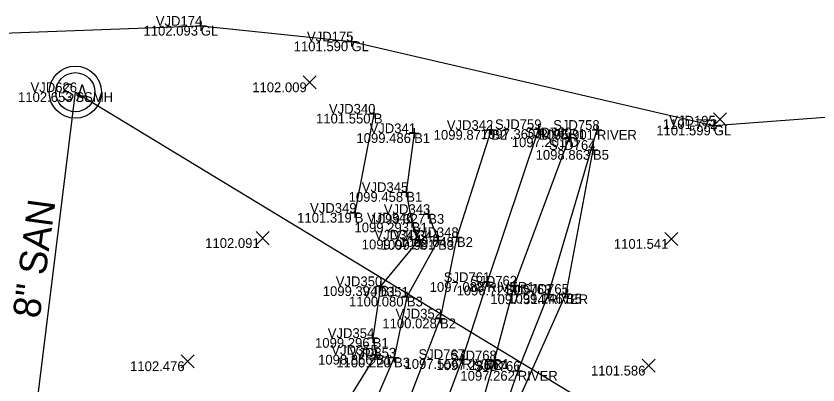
# Model space of a CAD drawing. Extents: x 1629915 to 1630675, y 484401 to 484601.
# Drawn here: x 1630255.7 to 1630337.7, y 484537.9 to 484575.6 of the extents above; entities that cross this region are included whole.
import ezdxf

# ---------------------------------------------------------------- set-up
doc = ezdxf.new("R2010")
doc.units = 0
for name, color, linetype in [('DR_X_Ditch', 7, 'Continuous'), ('GK_Drainage_Nodes', 7, 'Continuous'), ('HY_X_Water_Edge', 7, 'Continuous'), ('SV_X_Break_Lines', 7, 'Continuous'), ('SV_X_Random_Point', 7, 'Continuous'), ('SV_X_Shot_Marker', 7, 'Continuous'), ('SV_X_Text_Comment', 7, 'Continuous'), ('SV_X_Text_Elevation', 7, 'Continuous'), ('SV_X_Text_Name', 7, 'Continuous'), ('TX_X_20', 7, 'Continuous'), ('UT_X_Gas', 7, 'Continuous'), ('UT_X_Sanitary_Cells', 7, 'Continuous'), ('UT_X_Sanitary_Line', 7, 'Continuous')]:
    doc.layers.add(name, color=color, linetype=linetype)

msp = doc.modelspace()

# ---------------------------------------------------------------- linework, layer by layer
at = {"layer": 'DR_X_Ditch'}
msp.add_lwpolyline([(1630312.285, 484563.174), (1630306.638, 484548.008), (1630304.593, 484540.369), (1630301.212, 484528.393), (1630285.162, 484501.971), (1630282.791, 484487.89), (1630276.09, 484465.226), (1630270.913, 484444.523), (1630257.639, 484422.19), (1630254.188, 484411.475)], dxfattribs=at)
at = {"layer": 'GK_Drainage_Nodes'}
for p, q in [((1630261.76, 484569.794), (1630261.76, 484569.794)), ((1630261.76, 484567.794), (1630261.76, 484567.794)), ((1630261.76, 484567.794), (1630261.76, 484567.794)), ((1630261.76, 484567.794), (1630261.76, 484567.794)), ((1630261.76, 484565.794), (1630261.76, 484565.794))]:
    msp.add_line(p, q, dxfattribs=at)
msp.add_circle((1630261.76, 484567.794), 2, dxfattribs=at)
at = {"layer": 'HY_X_Water_Edge'}
for points in [[(1630309.149, 484564.014), (1630303.907, 484548.371), (1630301.335, 484540.498), (1630297.554, 484530.327), (1630293.047, 484517.737), (1630293.065, 484517.242), (1630286.863, 484512.402), (1630280.864, 484506.48), (1630276.95, 484506.557), (1630270.552, 484490.946), (1630261.424, 484466.626), (1630255.81, 484461.657), (1630255.926, 484458.148), (1630258.606, 484455.59), (1630264.105, 484457.697), (1630265.615, 484457.846), (1630266.742, 484455.334), (1630264.827, 484450.845), (1630263.176, 484437.258), (1630258.725, 484424.768), (1630254.124, 484415.998)], [(1630315.117, 484563.934), (1630310.133, 484547.118), (1630307.022, 484539.287), (1630303.337, 484528.643), (1630300.614, 484515.043), (1630303.987, 484512.284), (1630295.569, 484489.654), (1630286.814, 484467.342), (1630288.813, 484458.618), (1630286.633, 484457.39), (1630280.042, 484444.765), (1630267.68, 484419.987), (1630256.457, 484407.968)]]:
    msp.add_lwpolyline(points, dxfattribs=at)
at = {"layer": 'SV_X_Break_Lines'}
for points in [[(1630292.294, 484565.594), (1630290.337, 484555.453)], [(1630296.417, 484563.601), (1630295.615, 484557.584), (1630296.178, 484554.459), (1630296.937, 484552.722), (1630292.991, 484547.948), (1630292.183, 484542.654), (1630292.496, 484540.935), (1630289.335, 484535.783)], [(1630304.314, 484563.932), (1630300.799, 484552.969), (1630299.066, 484544.645), (1630294.605, 484533.045)], [(1630314.711, 484561.886), (1630311.942, 484547.182), (1630307.141, 484536.414), (1630304.819, 484528.662), (1630303.788, 484518.017)], [(1630297.86, 484555.334), (1630298.878, 484552.674), (1630295.673, 484546.879), (1630294.364, 484540.646), (1630291.461, 484533.951)]]:
    msp.add_lwpolyline(points, dxfattribs=at)
at = {"layer": 'SV_X_Random_Point'}
for p, q in [((1630285.071, 484568.127), (1630286.404, 484569.462)), ((1630285.071, 484569.462), (1630286.404, 484568.127)), ((1630327.059, 484564.358), (1630328.392, 484565.693)), ((1630327.059, 484565.693), (1630328.392, 484564.358)), ((1630280.257, 484552.196), (1630281.59, 484553.531)), ((1630280.257, 484553.531), (1630281.59, 484552.196)), ((1630322.065, 484552.107), (1630323.398, 484553.442)), ((1630322.065, 484553.442), (1630323.398, 484552.107)), ((1630272.594, 484539.599), (1630273.928, 484540.934)), ((1630272.594, 484540.934), (1630273.928, 484539.599)), ((1630319.74, 484539.15), (1630321.074, 484540.485)), ((1630319.74, 484540.485), (1630321.074, 484539.15))]:
    msp.add_line(p, q, dxfattribs=at)
at = {"layer": 'SV_X_Shot_Marker'}
for p, q in [((1630274.591, 484575.083), (1630274.591, 484574.083)), ((1630274.091, 484574.583), (1630275.091, 484574.583)), ((1630274.591, 484574.583), (1630274.591, 484574.583)), ((1630290.006, 484573.484), (1630290.006, 484572.484)), ((1630289.506, 484572.984), (1630290.506, 484572.984)), ((1630290.006, 484572.984), (1630290.006, 484572.984)), ((1630292.294, 484566.094), (1630292.294, 484565.094)), ((1630291.794, 484565.594), (1630292.794, 484565.594)), ((1630292.294, 484565.594), (1630292.294, 484565.594)), ((1630304.314, 484564.432), (1630304.314, 484563.432)), ((1630309.149, 484564.514), (1630309.149, 484563.514)), ((1630315.117, 484564.434), (1630315.117, 484563.434)), ((1630326.57, 484564.379), (1630327.57, 484564.379)), ((1630327.07, 484564.879), (1630327.07, 484563.879)), ((1630327.07, 484564.379), (1630327.07, 484564.379)), ((1630295.917, 484563.601), (1630296.917, 484563.601)), ((1630296.417, 484564.101), (1630296.417, 484563.101)), ((1630296.417, 484563.601), (1630296.417, 484563.601)), ((1630303.814, 484563.932), (1630304.814, 484563.932)), ((1630304.314, 484563.932), (1630304.314, 484563.932)), ((1630308.649, 484564.014), (1630309.649, 484564.014)), ((1630309.149, 484564.014), (1630309.149, 484564.014)), ((1630312.285, 484563.674), (1630312.285, 484562.674)), ((1630314.617, 484563.934), (1630315.617, 484563.934)), ((1630315.117, 484563.934), (1630315.117, 484563.934)), ((1630311.785, 484563.174), (1630312.785, 484563.174)), ((1630312.285, 484563.174), (1630312.285, 484563.174)), ((1630314.211, 484561.886), (1630315.211, 484561.886)), ((1630314.711, 484562.386), (1630314.711, 484561.386)), ((1630314.711, 484561.886), (1630314.711, 484561.886)), ((1630295.115, 484557.584), (1630296.115, 484557.584)), ((1630295.615, 484558.084), (1630295.615, 484557.084)), ((1630295.615, 484557.584), (1630295.615, 484557.584)), ((1630290.337, 484555.953), (1630290.337, 484554.953)), ((1630289.837, 484555.453), (1630290.837, 484555.453)), ((1630290.337, 484555.453), (1630290.337, 484555.453)), ((1630297.36, 484555.334), (1630298.36, 484555.334)), ((1630297.86, 484555.834), (1630297.86, 484554.834)), ((1630297.86, 484555.334), (1630297.86, 484555.334)), ((1630295.678, 484554.459), (1630296.678, 484554.459)), ((1630296.178, 484554.959), (1630296.178, 484553.959)), ((1630296.178, 484554.459), (1630296.178, 484554.459)), ((1630300.799, 484553.469), (1630300.799, 484552.469)), ((1630296.437, 484552.722), (1630297.437, 484552.722)), ((1630296.937, 484553.222), (1630296.937, 484552.222)), ((1630296.937, 484552.722), (1630296.937, 484552.722)), ((1630298.378, 484552.674), (1630299.378, 484552.674)), ((1630298.878, 484553.174), (1630298.878, 484552.174)), ((1630298.878, 484552.674), (1630298.878, 484552.674)), ((1630300.299, 484552.969), (1630301.299, 484552.969)), ((1630300.799, 484552.969), (1630300.799, 484552.969)), ((1630303.907, 484548.871), (1630303.907, 484547.871)), ((1630292.491, 484547.948), (1630293.491, 484547.948)), ((1630292.991, 484548.448), (1630292.991, 484547.448)), ((1630292.991, 484547.948), (1630292.991, 484547.948)), ((1630303.407, 484548.371), (1630304.407, 484548.371)), ((1630303.907, 484548.371), (1630303.907, 484548.371)), ((1630306.138, 484548.008), (1630307.138, 484548.008)), ((1630306.638, 484548.508), (1630306.638, 484547.508)), ((1630306.638, 484548.008), (1630306.638, 484548.008)), ((1630295.673, 484547.379), (1630295.673, 484546.379)), ((1630309.633, 484547.118), (1630310.633, 484547.118)), ((1630310.133, 484547.618), (1630310.133, 484546.618)), ((1630310.133, 484547.118), (1630310.133, 484547.118)), ((1630311.442, 484547.182), (1630312.442, 484547.182)), ((1630311.942, 484547.682), (1630311.942, 484546.682)), ((1630311.942, 484547.182), (1630311.942, 484547.182)), ((1630295.173, 484546.879), (1630296.173, 484546.879)), ((1630295.673, 484546.879), (1630295.673, 484546.879)), ((1630298.566, 484544.645), (1630299.566, 484544.645)), ((1630299.066, 484545.145), (1630299.066, 484544.145)), ((1630299.066, 484544.645), (1630299.066, 484544.645)), ((1630292.183, 484543.154), (1630292.183, 484542.154)), ((1630291.683, 484542.654), (1630292.683, 484542.654)), ((1630292.183, 484542.654), (1630292.183, 484542.654)), ((1630292.496, 484541.435), (1630292.496, 484540.435)), ((1630291.996, 484540.935), (1630292.996, 484540.935)), ((1630292.496, 484540.935), (1630292.496, 484540.935)), ((1630293.864, 484540.646), (1630294.864, 484540.646)), ((1630294.364, 484541.146), (1630294.364, 484540.146)), ((1630294.364, 484540.646), (1630294.364, 484540.646)), ((1630300.835, 484540.498), (1630301.835, 484540.498)), ((1630301.335, 484540.998), (1630301.335, 484539.998)), ((1630301.335, 484540.498), (1630301.335, 484540.498)), ((1630304.093, 484540.369), (1630305.093, 484540.369)), ((1630304.593, 484540.869), (1630304.593, 484539.869)), ((1630304.593, 484540.369), (1630304.593, 484540.369)), ((1630307.022, 484539.787), (1630307.022, 484538.787)), ((1630306.522, 484539.287), (1630307.522, 484539.287)), ((1630307.022, 484539.287), (1630307.022, 484539.287))]:
    msp.add_line(p, q, dxfattribs=at)
at = {"layer": 'UT_X_Gas'}
for points in [[(1630098.571, 484496.166), (1630109.658, 484497.037), (1630113.017, 484497.698), (1630113.953, 484498.758), (1630114.05, 484508.257), (1630114.557, 484509.569), (1630115.808, 484510.855), (1630129.42, 484519.99), (1630159.397, 484536.236), (1630181.581, 484547.984), (1630213.122, 484562.006), (1630240.482, 484573.334), (1630274.591, 484574.583), (1630290.006, 484572.984), (1630327.07, 484564.379), (1630366.658, 484567.361), (1630393.117, 484565.898), (1630419.955, 484549.235), (1630440.635, 484526.36), (1630450.487, 484510.253), (1630452.083, 484508.491), (1630453.278, 484508.551), (1630468.94, 484509.134)], [(1630098.571, 484496.166), (1630109.658, 484497.037), (1630113.017, 484497.698), (1630113.953, 484498.758), (1630114.05, 484508.257), (1630114.557, 484509.569), (1630115.808, 484510.855), (1630129.42, 484519.99), (1630159.397, 484536.236), (1630181.581, 484547.984), (1630213.122, 484562.006), (1630240.482, 484573.334), (1630274.591, 484574.583), (1630290.006, 484572.984), (1630327.07, 484564.379), (1630366.658, 484567.361), (1630393.117, 484565.898), (1630419.955, 484549.235), (1630440.635, 484526.36), (1630450.487, 484510.253), (1630452.083, 484508.491), (1630453.278, 484508.551), (1630494.384, 484510.081)]]:
    msp.add_lwpolyline(points, dxfattribs=at)
at = {"layer": 'UT_X_Sanitary_Cells'}
for points in [[(1630261.428, 484568.48), (1630261.403, 484568.505), (1630261.365, 484568.53), (1630261.251, 484568.568), (1630261.113, 484568.594), (1630261.012, 484568.594), (1630260.974, 484568.594), (1630260.81, 484568.556), (1630260.672, 484568.48), (1630260.584, 484568.379), (1630260.559, 484568.278), (1630260.559, 484568.203), (1630260.584, 484568.102), (1630260.684, 484568.014), (1630261.377, 484567.636), (1630261.44, 484567.586), (1630261.466, 484567.535), (1630261.491, 484567.46), (1630261.491, 484567.384), (1630261.478, 484567.309), (1630261.466, 484567.258), (1630261.44, 484567.195), (1630261.415, 484567.145), (1630261.39, 484567.107), (1630261.352, 484567.069), (1630261.314, 484567.044), (1630261.264, 484567.019), (1630261.226, 484567.006), (1630261.113, 484566.994), (1630260.936, 484566.994), (1630260.823, 484567.019), (1630260.659, 484567.107), (1630260.559, 484567.183)], [(1630261.969, 484566.994), (1630262.473, 484568.594), (1630262.965, 484566.994)], [(1630262.839, 484567.371), (1630262.095, 484567.371)]]:
    msp.add_lwpolyline(points, dxfattribs=at)
for radius in [2.667, 2]:
    msp.add_circle((1630261.76, 484567.794), radius, dxfattribs=at)
at = {"layer": 'UT_X_Sanitary_Line'}
msp.add_lwpolyline([(1629930.746, 484483.734), (1630048.132, 484488.308), (1630252.717, 484494.605), (1630261.76, 484567.793), (1630373.422, 484500.095), (1630654.857, 484509.349)], dxfattribs=at)

# ---------------------------------------------------------------- texts
at = {"layer": 'SV_X_Text_Comment'}
for s, p in [('GL', (1630274.591, 484573.583)), ('GL', (1630290.006, 484571.984)), ('SSMH', (1630261.76, 484566.794)), ('B', (1630292.294, 484564.594)), ('GL', (1630327.07, 484563.379)), ('B1', (1630296.417, 484562.601)), ('B2', (1630304.314, 484562.932)), ('RIVER1', (1630309.149, 484563.014)), ('RIVER', (1630315.117, 484562.934)), ('D', (1630312.285, 484562.174)), ('B5', (1630314.711, 484560.886)), ('B1', (1630295.615, 484556.584)), ('B', (1630290.337, 484554.453)), ('B3', (1630297.86, 484554.334)), ('B1', (1630296.178, 484553.459)), ('B1', (1630296.937, 484551.722)), ('B3', (1630298.878, 484551.674)), ('B2', (1630300.799, 484551.969)), ('B1', (1630292.991, 484546.948)), ('RIVER1', (1630303.907, 484547.371)), ('D', (1630306.638, 484547.008)), ('RIVER', (1630310.133, 484546.118)), ('B5', (1630311.942, 484546.182)), ('B3', (1630295.673, 484545.879)), ('B2', (1630299.066, 484543.645)), ('B1', (1630292.183, 484541.654)), ('B1', (1630292.496, 484539.935)), ('B3', (1630294.364, 484539.646)), ('RIVER1', (1630301.335, 484539.498)), ('D', (1630304.593, 484539.369)), ('RIVER', (1630307.022, 484538.287))]:
    msp.add_text(s, height=1, dxfattribs=at).set_placement(p)
at = {"layer": 'SV_X_Text_Elevation'}
for s, p in [('1102.093', (1630268.729, 484573.583)), ('1101.590', (1630284.094, 484571.984)), ('1102.009', (1630279.856, 484567.795)), ('1102.653', (1630255.898, 484566.794)), ('1101.550', (1630286.382, 484564.594)), ('1101.772', (1630321.854, 484564.026)), ('1101.599', (1630321.188, 484563.379)), ('1099.486', (1630290.515, 484562.601)), ('1099.877', (1630298.42, 484562.932)), ('1097.360', (1630303.237, 484563.014)), ('1096.901', (1630309.237, 484562.934)), ('1097.201', (1630306.405, 484562.174)), ('1098.863', (1630308.849, 484560.886)), ('1099.458', (1630289.716, 484556.584)), ('1101.319', (1630284.455, 484554.453)), ('1099.327', (1630291.966, 484554.334)), ('1099.293', (1630290.316, 484553.459)), ('1102.091', (1630275.044, 484551.863)), ('1099.071', (1630291.057, 484551.722)), ('1099.901', (1630292.999, 484551.674)), ('1099.648', (1630294.9, 484551.969)), ('1101.541', (1630316.852, 484551.774)), ('1099.394', (1630287.071, 484546.948)), ('1097.088', (1630298.009, 484547.371)), ('1096.721', (1630300.758, 484547.008)), ('1097.314', (1630304.213, 484546.118)), ('1099.146', (1630306.04, 484546.182)), ('1100.080', (1630289.761, 484545.879)), ('1100.028', (1630293.167, 484543.645)), ('1099.296', (1630286.281, 484541.654)), ('1098.866', (1630286.594, 484539.935)), ('1100.220', (1630288.452, 484539.646)), ('1097.556', (1630295.433, 484539.498)), ('1097.236', (1630298.691, 484539.369)), ('1102.476', (1630267.359, 484539.267)), ('1101.586', (1630314.505, 484538.817)), ('1097.262', (1630301.151, 484538.287))]:
    msp.add_text(s, height=1, dxfattribs=at).set_placement(p)
at = {"layer": 'SV_X_Text_Name'}
for s, p in [('VJD174', (1630269.989, 484574.583)), ('VJD175', (1630285.455, 484572.984)), ('VJD626', (1630257.176, 484567.794)), ('VJD340', (1630287.701, 484565.594)), ('VJD342', (1630299.761, 484563.932)), ('SJD759', (1630304.691, 484564.014)), ('SJD758', (1630310.642, 484563.934)), ('VJD195', (1630322.519, 484564.379)), ('VJD341', (1630291.855, 484563.601)), ('SJD760', (1630307.797, 484563.174)), ('SJD764', (1630310.214, 484561.886)), ('VJD345', (1630291.064, 484557.584)), ('VJD349', (1630285.773, 484555.453)), ('VJD343', (1630293.317, 484555.334)), ('VJD346', (1630291.594, 484554.459)), ('VJD347', (1630292.361, 484552.722)), ('VJD344', (1630294.277, 484552.674)), ('VJD348', (1630296.219, 484552.969)), ('SJD761', (1630299.451, 484548.371)), ('VJD350', (1630288.398, 484547.948)), ('SJD762', (1630302.19, 484548.008)), ('VJD351', (1630291.111, 484546.879)), ('SJD763', (1630305.695, 484547.118)), ('SJD765', (1630307.497, 484547.182)), ('VJD352', (1630294.512, 484544.645)), ('VJD354', (1630287.581, 484542.654)), ('VJD355', (1630287.946, 484540.935)), ('VJD353', (1630289.82, 484540.646)), ('SJD767', (1630296.865, 484540.498)), ('SJD768', (1630300.118, 484540.369)), ('SJD766', (1630302.543, 484539.287))]:
    msp.add_text(s, height=1, dxfattribs=at).set_placement(p)
at = {"layer": 'TX_X_20'}
msp.add_text('8" SAN', height=2.8, rotation=82.28682, dxfattribs=at).set_placement((1630258.104, 484544.58))

doc.saveas('drawing.dxf')
